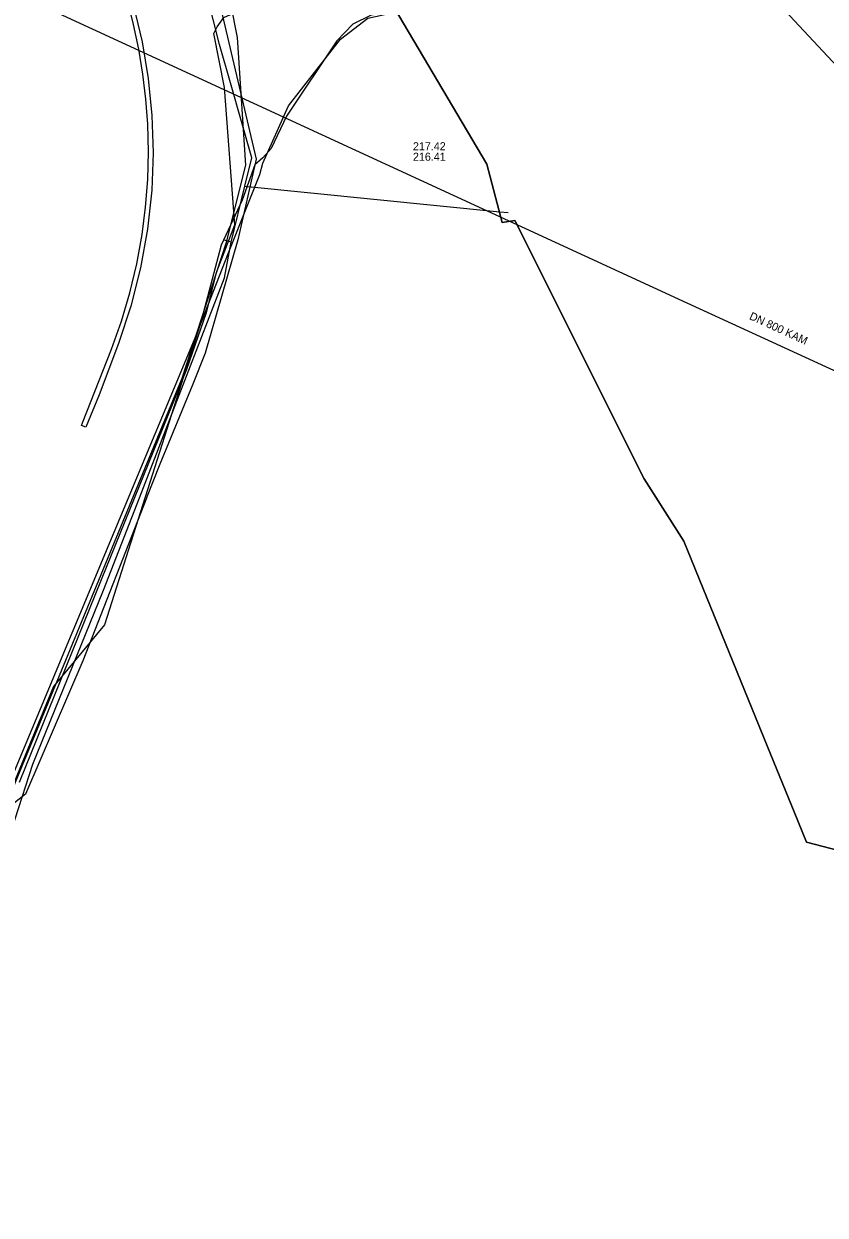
# Model space of a CAD drawing. Extents: x -598233 to -596890, y -1157848 to -1156431.
# Drawn here: x -598018 to -597937.9, y -1157271.2 to -1157152.1 of the extents above; entities that cross this region are included whole.
import ezdxf

# ---------------------------------------------------------------- set-up
doc = ezdxf.new("R2010")
doc.units = 0
for name, color, linetype in [('Vrstva 13', 7, 'Continuous'), ('Vrstva 15', 7, 'Continuous'), ('Vrstva 16', 7, 'Continuous'), ('Vrstva 3', 7, 'Continuous'), ('Vrstva 42', 7, 'Continuous'), ('Vrstva 44', 7, 'Continuous'), ('Vrstva 5', 7, 'Continuous'), ('Vrstva 54', 7, 'Continuous'), ('Vrstva 55', 7, 'Continuous'), ('Vrstva 60', 7, 'Continuous'), ('Vrstva 8', 7, 'Continuous')]:
    doc.layers.add(name, color=color, linetype=linetype)

msp = doc.modelspace()

# ---------------------------------------------------------------- linework, layer by layer
at = {"layer": 'Vrstva 13'}
for points in [[(-598023.6, -1157246), (-598021.15, -1157238.55), (-598020.66, -1157237.06), (-598017.11, -1157226.12), (-598010.04, -1157208.72), (-598006.43, -1157199.48), (-597997.93, -1157177.49), (-597997.27, -1157173.94), (-597995.9, -1157168.34), (-597995.2, -1157165.5), (-597997.27, -1157158.26), (-597998.43, -1157154.17), (-598000.38, -1157146.53), (-598006.13, -1157120.8), (-598011.08, -1157097.12), (-598013.03, -1157087.24), (-598013.16, -1157086.66)], [(-597995.9, -1157168.34), (-597995.62, -1157168.38), (-597970.41, -1157170.91), (-597969.58, -1157170.98)], [(-597997.27, -1157173.94), (-597997.53, -1157173.86), (-597998.05, -1157173.72)]]:
    msp.add_lwpolyline(points, dxfattribs=at)
at = {"layer": 'Vrstva 15'}
for points in [[(-598177.7, -1157331.44), (-598171.06, -1157324.28), (-598141.13, -1157273.38), (-598121.67, -1157262.01), (-598109.06, -1157260.24), (-598080.97, -1157256.77), (-598048.03, -1157253.89), (-598040.96, -1157252.57), (-598036.72, -1157251.12), (-598031.8, -1157248.6), (-598029.05, -1157246.45), (-598026.12, -1157243.44), (-598023.52, -1157239.57), (-598020.59, -1157232.1), (-598002.18, -1157187.53), (-597997.74, -1157173.94), (-597995.79, -1157166.26), (-597996.65, -1157153.48), (-598000.07, -1157136.13), (-598006.2, -1157117.94), (-598011.01, -1157099.85), (-598013.68, -1157085.44), (-598015.3, -1157071.94), (-598015.06, -1157065.07)], [(-597923.68, -1157170.4), (-597927.69, -1157166.8), (-597934.81, -1157158.41), (-597958.07, -1157133.48), (-597968.63, -1157121.57), (-597977.65, -1157110.04), (-597984.68, -1157101.26), (-597991.46, -1157093.59), (-598005.37, -1157077.6), (-598015.06, -1157065.07)]]:
    msp.add_lwpolyline(points, dxfattribs=at)
at = {"layer": 'Vrstva 16'}
msp.add_lwpolyline([(-598022.77, -1157085.78), (-598014.26, -1157085.46), (-598012, -1157085.4), (-598010.02, -1157097.15), (-598010.54, -1157098.54), (-598010.13, -1157100.67), (-598009.25, -1157101.74), (-598003.49, -1157128.4), (-597998.83, -1157146.23), (-597998.36, -1157150.13), (-597998.18, -1157151.19), (-597994.77, -1157165.65), (-597996.59, -1157173.71), (-597999.87, -1157185.03), (-598001.1, -1157188.15), (-598004.4, -1157196.12), (-598005.72, -1157199.5), (-598005.73, -1157199.53), (-598012.09, -1157215.8), (-598017.82, -1157229.11), (-598018.92, -1157230)], dxfattribs=at)
at = {"layer": 'Vrstva 3'}
msp.add_lwpolyline([(-598007.7, -1157147.53), (-598006.18, -1157153.9), (-598005.57, -1157157.57), (-598005.21, -1157161.28), (-598005.08, -1157165.01), (-598005.2, -1157168.73), (-598005.62, -1157172.64), (-598006.32, -1157176.52), (-598007.29, -1157180.33), (-598008.52, -1157184.07), (-598010.48, -1157189.19), (-598011.79, -1157192.42), (-598012.22, -1157192.25), (-598012.12, -1157192), (-598009.23, -1157184.65), (-598008.24, -1157181.85), (-598007.4, -1157178.99), (-598006.71, -1157176.1), (-598006.17, -1157173.18), (-598005.82, -1157170.44), (-598005.61, -1157167.68), (-598005.53, -1157164.92), (-598005.6, -1157162.16), (-598005.79, -1157159.65), (-598006.09, -1157157.14), (-598006.51, -1157154.66), (-598007.04, -1157152.19), (-598008.12, -1157147.6)], dxfattribs=at)
at = {"layer": 'Vrstva 42'}
for points in [[(-597971.82, -1157138.71), (-597971.84, -1157139.04), (-597972.21, -1157139.1), (-597974.25, -1157139.43), (-597974.61, -1157139.49), (-597977.42, -1157140.7), (-597977.52, -1157140.95), (-597977.53, -1157140.97), (-597977.65, -1157141.26), (-597977.51, -1157141.78), (-597975.49, -1157147.46), (-597975.79, -1157148.14), (-597979.28, -1157149.68), (-597979.96, -1157150.58), (-597980.95, -1157150.92), (-597983.28, -1157151.24), (-597985.1, -1157152.15), (-597986.7, -1157153.83), (-597991.74, -1157161.33), (-597993.26, -1157164.59), (-597994.11, -1157165.51)], [(-597994.11, -1157165.51), (-597994.92, -1157166.2), (-597996.16, -1157169.74), (-597998.28, -1157174.23), (-598000.36, -1157182.17), (-598009.94, -1157212.19), (-598015.02, -1157218.37), (-598020.5, -1157231.59), (-598020.56, -1157234.19), (-598020.82, -1157236.54), (-598023.04, -1157240.51), (-598026.4, -1157244.91), (-598032.53, -1157251.35), (-598040.34, -1157254.97), (-598050.72, -1157255.94), (-598059.57, -1157256.38), (-598071.24, -1157257.32), (-598081.99, -1157259.52), (-598091.17, -1157260.9), (-598148.19, -1157272.75), (-598150.22, -1157273.09)]]:
    msp.add_lwpolyline(points, dxfattribs=at)
at = {"layer": 'Vrstva 44'}
for points in [[(-597998.99, -1157153.07), (-597998.68, -1157152.41), (-597997.99, -1157151.49), (-597997.33, -1157151.17), (-597996.57, -1157150.66), (-597991.74, -1157147.43), (-597978.64, -1157142.78), (-597978.02, -1157141.59), (-597977.15, -1157141.02), (-597971.54, -1157139.35), (-597959.76, -1157134.81), (-597951.54, -1157131.89), (-597944.74, -1157129.42), (-597943.76, -1157128.89)], [(-598018.43, -1157227.91), (-598010.22, -1157207.67), (-598001.69, -1157186.63), (-597999.75, -1157180.97), (-597998.7, -1157176.87), (-597996.91, -1157172.21), (-597997.95, -1157158.48), (-597998.99, -1157153.07)]]:
    msp.add_lwpolyline(points, dxfattribs=at)
at = {"layer": 'Vrstva 5'}
msp.add_line((-598070.53, -1157125.26), (-597975.07, -1157169.23), dxfattribs=at)
msp.add_lwpolyline([(-597975.07, -1157169.23), (-597951.71, -1157179.99), (-597907.24, -1157200.44), (-597885.59, -1157210.4)], dxfattribs=at)
at = {"layer": 'Vrstva 54'}
for p, q in [((-597981.47, -1157149.61), (-597971.72, -1157166.16)), ((-597971.72, -1157166.16), (-597970.17, -1157171.99)), ((-597970.17, -1157171.99), (-597968.92, -1157171.76)), ((-597968.92, -1157171.76), (-597955.98, -1157197.6)), ((-597955.98, -1157197.6), (-597952.02, -1157203.83)), ((-597952.02, -1157203.83), (-597943.32, -1157225.19)), ((-597943.32, -1157225.19), (-597941, -1157230.87)), ((-597941, -1157230.87), (-597939.77, -1157233.9)), ((-597939.77, -1157233.9), (-597929.67, -1157236.56))]:
    msp.add_line(p, q, dxfattribs=at)
at = {"layer": 'Vrstva 55'}
for points in [[(-597994.39, -1157167.18), (-597994.11, -1157166.03), (-597991.54, -1157160.3), (-597986.35, -1157153.64), (-597983.61, -1157151.56), (-597981.01, -1157150.99), (-597979.82, -1157150.3), (-597976.86, -1157148.32), (-597973.35, -1157147.45), (-597976.86, -1157148.32), (-597978.73, -1157140.94)], [(-598025.39, -1157242.25), (-598000.77, -1157183.28), (-597997.53, -1157175.02), (-597994.39, -1157167.18)]]:
    msp.add_lwpolyline(points, dxfattribs=at)
at = {"layer": 'Vrstva 60'}
for points in [[(-597981.47, -1157149.61), (-597971.72, -1157166.16), (-597970.17, -1157171.99), (-597968.92, -1157171.76), (-597955.98, -1157197.6), (-597952.02, -1157203.83), (-597943.32, -1157225.19), (-597941, -1157230.87), (-597939.77, -1157233.9), (-597929.67, -1157236.56), (-597923.63, -1157238.02), (-597882.54, -1157247.95), (-597875.91, -1157249.55), (-597833.74, -1157262.53), (-597802.08, -1157274.42)], [(-597802.08, -1157274.42), (-597833.74, -1157262.53), (-597875.91, -1157249.55), (-597882.54, -1157247.95), (-597923.63, -1157238.02), (-597929.67, -1157236.56), (-597939.77, -1157233.9), (-597941, -1157230.87), (-597943.32, -1157225.19), (-597952.02, -1157203.83), (-597955.98, -1157197.6), (-597968.92, -1157171.76), (-597970.17, -1157171.99), (-597971.72, -1157166.16), (-597981.47, -1157149.61)]]:
    msp.add_lwpolyline(points, dxfattribs=at)

# ---------------------------------------------------------------- texts
at = {"layer": 'Vrstva 8'}
for s, p in [('217.42', (-597979.1, -1157164.75)), ('216.41', (-597979.1, -1157165.8))]:
    msp.add_text(s, height=0.8, dxfattribs=at).set_placement(p)
msp.add_text('DN 800 KAM', height=0.8, rotation=335.2949, dxfattribs=at).set_placement((-597945.55, -1157181.61))

doc.saveas('drawing.dxf')
